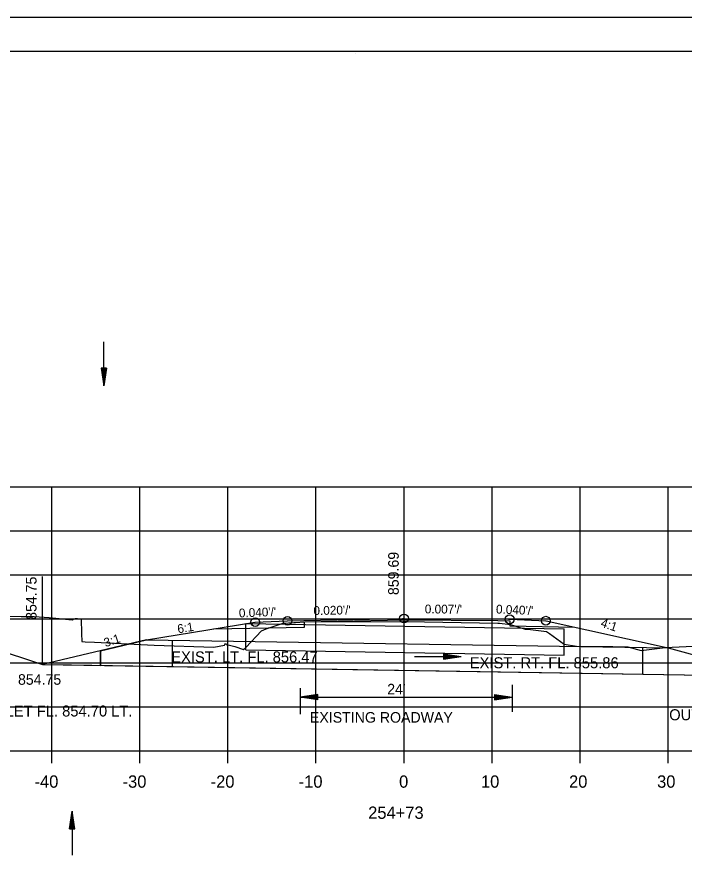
# Model space of a CAD drawing. Extents: x 1486524 to 1499135, y 326561 to 337924.
# Drawn here: x 1488938.9 to 1489014.8, y 328415.9 to 328512.5 of the extents above; entities that cross this region are included whole.
import ezdxf

# ---------------------------------------------------------------- set-up
doc = ezdxf.new("R2010")
doc.units = 0
for name, color, linetype in [('E_Const Align', 7, 'Continuous'), ('E_Const Align Station', 7, 'Continuous'), ('E_Ownership Information', 7, 'Continuous'), ('E_Property Line', 7, 'Continuous'), ('E_Proposed ROW and Easements', 7, 'Continuous'), ('E_Proposed ROW Fig Annot', 7, 'Continuous'), ('E_Quarter Calls', 7, 'Continuous'), ('E_Station Offset', 7, 'Continuous'), ('R_Water Annot', 7, 'Continuous'), ('R_Xsect Elev', 7, 'Continuous'), ('T_Notes', 7, 'Continuous')]:
    doc.layers.add(name, color=color, linetype=linetype)

msp = doc.modelspace()

# ---------------------------------------------------------------- linework, layer by layer
at = {"layer": 'E_Const Align'}
for p, q in [((1488962.883, 328437.793), (1488962.883, 328439.193)), ((1488972.883, 328437.793), (1488972.883, 328439.193)), ((1488982.883, 328437.793), (1488982.883, 328439.193)), ((1488992.883, 328437.793), (1488992.883, 328439.193)), ((1489002.883, 328437.793), (1489002.883, 328439.193)), ((1489012.883, 328437.793), (1489012.883, 328439.193)), ((1488842.885, 328429.191), (1489122.885, 328429.191)), ((1488942.885, 328427.791), (1488942.885, 328429.191)), ((1488952.885, 328427.791), (1488952.885, 328429.191)), ((1488962.885, 328427.791), (1488962.885, 328429.191)), ((1488972.885, 328427.791), (1488972.885, 328429.191)), ((1488982.885, 328427.791), (1488982.885, 328429.191)), ((1488992.885, 328427.791), (1488992.885, 328429.191)), ((1489002.885, 328427.791), (1489002.885, 328429.191)), ((1489012.885, 328427.791), (1489012.885, 328429.191))]:
    msp.add_line(p, q, dxfattribs=at)
at = {"layer": 'E_Ownership Information'}
for p, q in [((1488842.885, 328459.191), (1489122.885, 328459.191)), ((1488942.885, 328429.191), (1488942.885, 328459.191)), ((1488952.885, 328429.191), (1488952.885, 328459.191)), ((1488962.885, 328429.191), (1488962.885, 328459.191)), ((1488972.885, 328429.191), (1488972.885, 328459.191)), ((1488982.885, 328429.191), (1488982.885, 328459.191)), ((1488992.885, 328429.191), (1488992.885, 328459.191)), ((1489002.885, 328429.191), (1489002.885, 328459.191)), ((1489012.885, 328429.191), (1489012.885, 328459.191)), ((1488842.885, 328454.191), (1489122.885, 328454.191)), ((1488842.885, 328449.191), (1489122.885, 328449.191)), ((1488842.885, 328444.191), (1489122.885, 328444.191)), ((1488842.885, 328439.191), (1489122.885, 328439.191)), ((1488842.885, 328434.191), (1489122.885, 328434.191)), ((1488842.885, 328429.191), (1489122.885, 328429.191))]:
    msp.add_line(p, q, dxfattribs=at)
at = {"layer": 'E_Property Line'}
for p, q in [((1488824.885, 328508.651), (1489141.065, 328508.651)), ((1488977.405, 328508.391), (1488977.405, 328508.391)), ((1488977.405, 328508.391), (1488977.405, 328508.391))]:
    msp.add_line(p, q, dxfattribs=at)
at = {"layer": 'E_Proposed ROW and Easements'}
for p, q in [((1488964.913, 328440.663), (1488964.913, 328443.663)), ((1488964.913, 328443.663), (1489001.073, 328443.053)), ((1489001.073, 328440.053), (1489001.073, 328443.053)), ((1488964.913, 328440.663), (1489001.073, 328440.053)), ((1488995.154, 328436.671), (1488995.154, 328433.603)), ((1488971.086, 328436.285), (1488971.086, 328433.333)), ((1488973.086, 328435.584), (1488971.086, 328435.284)), ((1488973.086, 328435.534), (1488971.42, 328435.284)), ((1488973.086, 328435.483), (1488971.764, 328435.284)), ((1488973.086, 328435.433), (1488972.097, 328435.284)), ((1488973.086, 328435.382), (1488972.436, 328435.284)), ((1488973.086, 328434.984), (1488973.086, 328435.584)), ((1488993.154, 328435.589), (1488995.154, 328435.289)), ((1488993.154, 328435.589), (1488993.154, 328434.989)), ((1488993.154, 328435.539), (1488994.82, 328435.289)), ((1488993.154, 328435.488), (1488994.476, 328435.289)), ((1488993.154, 328435.438), (1488994.143, 328435.289)), ((1488993.154, 328435.386), (1488993.804, 328435.289)), ((1488973.086, 328434.984), (1488971.086, 328435.284)), ((1488973.086, 328435.034), (1488971.42, 328435.284)), ((1488973.086, 328435.085), (1488971.764, 328435.284)), ((1488973.086, 328435.135), (1488972.097, 328435.284)), ((1488973.086, 328435.187), (1488972.436, 328435.284)), ((1488973.086, 328435.331), (1488972.77, 328435.284)), ((1488973.086, 328435.237), (1488972.77, 328435.284)), ((1488993.154, 328435.336), (1488993.47, 328435.289)), ((1488993.154, 328434.989), (1488995.154, 328435.289)), ((1488993.154, 328435.191), (1488993.804, 328435.289)), ((1488993.154, 328435.09), (1488994.476, 328435.289)), ((1488993.154, 328435.039), (1488994.82, 328435.289)), ((1488993.154, 328435.14), (1488994.143, 328435.289)), ((1488993.154, 328435.242), (1488993.47, 328435.289))]:
    msp.add_line(p, q, dxfattribs=at)
at = {"layer": 'E_Proposed ROW Fig Annot'}
for p, q in [((1488948.5, 328472.648), (1488948.8, 328470.648)), ((1488949.1, 328472.648), (1488948.5, 328472.648)), ((1488948.5, 328472.648), (1488948.8, 328470.648)), ((1488949.1, 328472.648), (1488948.5, 328472.648)), ((1488948.55, 328472.648), (1488948.8, 328470.982)), ((1488948.55, 328472.648), (1488948.8, 328470.982)), ((1488948.601, 328472.648), (1488948.8, 328471.326)), ((1488948.601, 328472.648), (1488948.8, 328471.326)), ((1488948.651, 328472.648), (1488948.8, 328471.659)), ((1488948.651, 328472.648), (1488948.8, 328471.659)), ((1488948.702, 328472.648), (1488948.8, 328471.998)), ((1488948.702, 328472.648), (1488948.8, 328471.998)), ((1488948.753, 328472.648), (1488948.8, 328472.332)), ((1488948.753, 328472.648), (1488948.8, 328472.332)), ((1488949.1, 328472.648), (1488948.8, 328470.648)), ((1488948.897, 328472.648), (1488948.8, 328471.998)), ((1488948.999, 328472.648), (1488948.8, 328471.326)), ((1488949.05, 328472.648), (1488948.8, 328470.982)), ((1488948.949, 328472.648), (1488948.8, 328471.659)), ((1488948.847, 328472.648), (1488948.8, 328472.332)), ((1488949.1, 328472.648), (1488948.8, 328470.648)), ((1488948.897, 328472.648), (1488948.8, 328471.998)), ((1488948.999, 328472.648), (1488948.8, 328471.326)), ((1488949.05, 328472.648), (1488948.8, 328470.982)), ((1488948.949, 328472.648), (1488948.8, 328471.659)), ((1488948.847, 328472.648), (1488948.8, 328472.332)), ((1488953.653, 328441.804), (1489012.884, 328440.868)), ((1488956.553, 328441.738), (1488956.553, 328438.738)), ((1488948.403, 328440.558), (1488948.403, 328438.888)), ((1488987.378, 328440.195), (1488989.378, 328439.895)), ((1488987.378, 328440.195), (1488987.378, 328439.595)), ((1489009.983, 328440.913), (1489009.983, 328437.897)), ((1488987.378, 328440.145), (1488989.044, 328439.895)), ((1488987.378, 328440.094), (1488988.7, 328439.895)), ((1488987.378, 328440.044), (1488988.367, 328439.895)), ((1488987.378, 328439.992), (1488988.028, 328439.895)), ((1488987.378, 328439.942), (1488987.694, 328439.895)), ((1488987.378, 328439.595), (1488989.378, 328439.895)), ((1488987.378, 328439.797), (1488988.028, 328439.895)), ((1488987.378, 328439.696), (1488988.7, 328439.895)), ((1488987.378, 328439.645), (1488989.044, 328439.895)), ((1488987.378, 328439.746), (1488988.367, 328439.895)), ((1488987.378, 328439.848), (1488987.694, 328439.895)), ((1488941.814, 328438.994), (1489022.333, 328437.698)), ((1488971.086, 328435.284), (1488995.154, 328435.289)), ((1488944.885, 328420.312), (1488945.185, 328422.312)), ((1488944.935, 328420.312), (1488945.185, 328421.978)), ((1488945.485, 328420.312), (1488945.185, 328422.312)), ((1488945.435, 328420.312), (1488945.185, 328421.978)), ((1488944.986, 328420.312), (1488945.185, 328421.634)), ((1488945.036, 328420.312), (1488945.185, 328421.301)), ((1488945.088, 328420.312), (1488945.185, 328420.962)), ((1488945.384, 328420.312), (1488945.185, 328421.634)), ((1488945.334, 328420.312), (1488945.185, 328421.301)), ((1488945.283, 328420.312), (1488945.185, 328420.962)), ((1488944.885, 328420.312), (1488945.485, 328420.312)), ((1488945.138, 328420.312), (1488945.185, 328420.628)), ((1488945.232, 328420.312), (1488945.185, 328420.628))]:
    msp.add_line(p, q, dxfattribs=at)
at = {"layer": 'E_Quarter Calls'}
msp.add_line((1488812.485, 328512.546), (1489145.818, 328512.546), dxfattribs=at)
for points in [[(1488812.478, 328512.546), (1489145.818, 328512.546), (1489145.818, 328299.208), (1488812.478, 328299.208)], [(1489058.805, 328508.651), (1489058.805, 328498.771), (1489094.538, 328498.771), (1489094.538, 328495.851), (1489117.737, 328495.851), (1489117.737, 328471.518), (1489141.065, 328471.518), (1489141.065, 328303.191), (1488824.885, 328303.191), (1488824.885, 328508.651)]]:
    msp.add_lwpolyline(points, close=True, dxfattribs=at)
for centre in [(1488969.653, 328443.949), (1488994.885, 328444.126), (1488994.885, 328444.126)]:
    msp.add_circle(centre, 0.5, dxfattribs=at)
at = {"layer": 'E_Station Offset'}
msp.add_line((1488953.653, 328441.804), (1488941.814, 328438.994), dxfattribs=at)
at = {"layer": 'R_Water Annot'}
for p, q in [((1488948.8, 328470.648), (1488948.8, 328475.648)), ((1488984.079, 328439.899), (1488989.079, 328439.899)), ((1488945.185, 328422.312), (1488945.185, 328417.312))]:
    msp.add_line(p, q, dxfattribs=at)
at = {"layer": 'R_Xsect Elev'}
for p, q in [((1488982.885, 328443.876), (1488982.885, 328453.876)), ((1488941.814, 328438.994), (1488941.814, 328448.974))]:
    msp.add_line(p, q, dxfattribs=at)
at = {"layer": 'T_Notes'}
for p, q in [((1488948.8, 328470.648), (1488948.8, 328475.648)), ((1488948.5, 328472.648), (1488948.8, 328470.648)), ((1488949.1, 328472.648), (1488948.5, 328472.648)), ((1488948.5, 328472.648), (1488948.8, 328470.648)), ((1488949.1, 328472.648), (1488948.5, 328472.648)), ((1488948.55, 328472.648), (1488948.8, 328470.982)), ((1488948.55, 328472.648), (1488948.8, 328470.982)), ((1488948.601, 328472.648), (1488948.8, 328471.326)), ((1488948.601, 328472.648), (1488948.8, 328471.326)), ((1488948.651, 328472.648), (1488948.8, 328471.659)), ((1488948.651, 328472.648), (1488948.8, 328471.659)), ((1488948.702, 328472.648), (1488948.8, 328471.998)), ((1488948.702, 328472.648), (1488948.8, 328471.998)), ((1488948.753, 328472.648), (1488948.8, 328472.332)), ((1488948.753, 328472.648), (1488948.8, 328472.332)), ((1488949.1, 328472.648), (1488948.8, 328470.648)), ((1488948.897, 328472.648), (1488948.8, 328471.998)), ((1488948.999, 328472.648), (1488948.8, 328471.326)), ((1488949.05, 328472.648), (1488948.8, 328470.982)), ((1488948.949, 328472.648), (1488948.8, 328471.659)), ((1488948.847, 328472.648), (1488948.8, 328472.332)), ((1488949.1, 328472.648), (1488948.8, 328470.648)), ((1488948.897, 328472.648), (1488948.8, 328471.998)), ((1488948.999, 328472.648), (1488948.8, 328471.326)), ((1488949.05, 328472.648), (1488948.8, 328470.982)), ((1488948.949, 328472.648), (1488948.8, 328471.659)), ((1488948.847, 328472.648), (1488948.8, 328472.332)), ((1488964.913, 328440.663), (1488964.913, 328443.663)), ((1488964.913, 328443.663), (1489001.073, 328443.053)), ((1488971.586, 328443.241), (1488971.586, 328443.241)), ((1489001.073, 328440.053), (1489001.073, 328443.053)), ((1488953.653, 328441.804), (1489012.884, 328440.868)), ((1488956.553, 328441.738), (1488956.553, 328438.738)), ((1488964.913, 328440.663), (1489001.073, 328440.053)), ((1488987.378, 328440.195), (1488989.378, 328439.895)), ((1488987.378, 328440.195), (1488987.378, 328439.595)), ((1489009.983, 328440.913), (1489009.983, 328437.897)), ((1488984.079, 328439.899), (1488989.079, 328439.899)), ((1488987.378, 328440.145), (1488989.044, 328439.895)), ((1488987.378, 328440.094), (1488988.7, 328439.895)), ((1488987.378, 328440.044), (1488988.367, 328439.895)), ((1488987.378, 328439.992), (1488988.028, 328439.895)), ((1488987.378, 328439.942), (1488987.694, 328439.895)), ((1488987.378, 328439.595), (1488989.378, 328439.895)), ((1488987.378, 328439.797), (1488988.028, 328439.895)), ((1488987.378, 328439.696), (1488988.7, 328439.895)), ((1488987.378, 328439.645), (1488989.044, 328439.895)), ((1488987.378, 328439.746), (1488988.367, 328439.895)), ((1488987.378, 328439.848), (1488987.694, 328439.895)), ((1488945.123, 328438.941), (1489022.333, 328437.698)), ((1488962.883, 328437.793), (1488962.883, 328439.193)), ((1488972.883, 328437.793), (1488972.883, 328439.193)), ((1488982.883, 328437.793), (1488982.883, 328439.193)), ((1488992.883, 328437.793), (1488992.883, 328439.193)), ((1489002.883, 328437.793), (1489002.883, 328439.193)), ((1489012.883, 328437.793), (1489012.883, 328439.193)), ((1488995.154, 328436.671), (1488995.154, 328433.603)), ((1488971.086, 328436.285), (1488971.086, 328433.333)), ((1488973.086, 328435.584), (1488971.086, 328435.284)), ((1488973.086, 328435.534), (1488971.42, 328435.284)), ((1488973.086, 328435.483), (1488971.764, 328435.284)), ((1488973.086, 328435.433), (1488972.097, 328435.284)), ((1488973.086, 328435.382), (1488972.436, 328435.284)), ((1488973.086, 328434.984), (1488973.086, 328435.584)), ((1488993.154, 328435.589), (1488995.154, 328435.289)), ((1488993.154, 328435.589), (1488993.154, 328434.989)), ((1488993.154, 328435.539), (1488994.82, 328435.289)), ((1488993.154, 328435.488), (1488994.476, 328435.289)), ((1488993.154, 328435.438), (1488994.143, 328435.289)), ((1488993.154, 328435.386), (1488993.804, 328435.289)), ((1488971.086, 328435.284), (1488995.154, 328435.289)), ((1488973.086, 328434.984), (1488971.086, 328435.284)), ((1488973.086, 328435.034), (1488971.42, 328435.284)), ((1488973.086, 328435.085), (1488971.764, 328435.284)), ((1488973.086, 328435.135), (1488972.097, 328435.284)), ((1488973.086, 328435.187), (1488972.436, 328435.284)), ((1488973.086, 328435.331), (1488972.77, 328435.284)), ((1488973.086, 328435.237), (1488972.77, 328435.284)), ((1488993.154, 328435.336), (1488993.47, 328435.289)), ((1488993.154, 328434.989), (1488995.154, 328435.289)), ((1488993.154, 328435.191), (1488993.804, 328435.289)), ((1488993.154, 328435.09), (1488994.476, 328435.289)), ((1488993.154, 328435.039), (1488994.82, 328435.289)), ((1488993.154, 328435.14), (1488994.143, 328435.289)), ((1488993.154, 328435.242), (1488993.47, 328435.289)), ((1488842.885, 328429.191), (1489122.885, 328429.191)), ((1488942.885, 328427.791), (1488942.885, 328429.191)), ((1488952.885, 328427.791), (1488952.885, 328429.191)), ((1488962.885, 328427.791), (1488962.885, 328429.191)), ((1488972.885, 328427.791), (1488972.885, 328429.191)), ((1488982.885, 328427.791), (1488982.885, 328429.191)), ((1488992.885, 328427.791), (1488992.885, 328429.191)), ((1489002.885, 328427.791), (1489002.885, 328429.191)), ((1489012.885, 328427.791), (1489012.885, 328429.191)), ((1488944.885, 328420.312), (1488945.185, 328422.312)), ((1488944.935, 328420.312), (1488945.185, 328421.978)), ((1488945.485, 328420.312), (1488945.185, 328422.312)), ((1488945.435, 328420.312), (1488945.185, 328421.978)), ((1488944.986, 328420.312), (1488945.185, 328421.634)), ((1488945.036, 328420.312), (1488945.185, 328421.301)), ((1488945.088, 328420.312), (1488945.185, 328420.962)), ((1488945.384, 328420.312), (1488945.185, 328421.634)), ((1488945.334, 328420.312), (1488945.185, 328421.301)), ((1488945.283, 328420.312), (1488945.185, 328420.962)), ((1488944.885, 328420.312), (1488945.485, 328420.312)), ((1488945.138, 328420.312), (1488945.185, 328420.628)), ((1488945.232, 328420.312), (1488945.185, 328420.628))]:
    msp.add_line(p, q, dxfattribs=at)
for points in [[(1488924.201, 328444.819), (1488941.814, 328438.994), (1488945.123, 328438.941), (1488948.403, 328438.888), (1488948.403, 328440.558), (1488953.653, 328441.804), (1488965.953, 328443.793), (1488965.991, 328443.803), (1488969.607, 328443.947), (1488969.653, 328443.949), (1488982.72, 328444.21), (1488982.885, 328444.214), (1488994.732, 328444.128), (1488994.885, 328444.126), (1488994.936, 328444.124), (1488998.989, 328443.962), (1488999.026, 328443.953), (1489012.883, 328440.868), (1489018.133, 328439.435), (1489018.133, 328437.765), (1489023.119, 328437.698), (1489062.966, 328440.404)], [(1488934.619, 328444.556), (1488939.407, 328444.453), (1488940.9, 328444.459), (1488942.589, 328444.333), (1488945.194, 328444.081), (1488945.397, 328444.167), (1488945.53, 328444.208), (1488945.82, 328444.197), (1488946.216, 328444.181), (1488946.251, 328442.503), (1488946.282, 328441.619), (1488946.67, 328441.563), (1488947.73, 328441.513), (1488954.501, 328441.198), (1488961.271, 328440.94), (1488962.497, 328441.181), (1488962.629, 328441.412), (1488962.698, 328441.272), (1488962.899, 328441.21), (1488963.683, 328441.03), (1488964.64, 328440.678), (1488964.921, 328440.927), (1488966.685, 328442.812), (1488967.211, 328443.024), (1488969.173, 328443.681), (1488970.389, 328443.758), (1488970.476, 328443.764), (1488970.544, 328443.767), (1488971.586, 328443.818), (1488982.735, 328443.875), (1488982.931, 328443.876), (1488983.141, 328443.873), (1488993.537, 328443.699), (1488993.729, 328443.677), (1488994.989, 328443.52), (1488996.661, 328443.003), (1488997.264, 328442.946), (1488999.062, 328442.722), (1488999.389, 328442.524), (1489001.087, 328441.294), (1489002.465, 328441.082), (1489004.257, 328441.044), (1489006.613, 328441.021), (1489008.295, 328440.982), (1489009.826, 328440.582), (1489012.538, 328440.92), (1489018.082, 328441.198)], [(1488961.262, 328443.035), (1488971.586, 328443.241), (1488971.586, 328443.821), (1488982.885, 328444.047), (1488993.537, 328443.969), (1488994.895, 328443.959), (1488994.895, 328443.379), (1489002.265, 328443.232)]]:
    msp.add_lwpolyline(points, dxfattribs=at)
for centre in [(1488965.991, 328443.803), (1488969.653, 328443.949), (1488969.653, 328443.949), (1488982.885, 328444.214), (1488982.885, 328444.214), (1488994.885, 328444.126), (1488994.885, 328444.126), (1488998.989, 328443.962), (1488998.989, 328443.962)]:
    msp.add_circle(centre, 0.5, dxfattribs=at)

# ---------------------------------------------------------------- texts
at = {"layer": 'E_Const Align Station'}
for s, p in [('-40', (1488940.924, 328424.991)), ('-30', (1488950.924, 328424.991)), ('-20', (1488960.924, 328424.991)), ('-10', (1488970.924, 328424.991)), ('0', (1488982.324, 328424.991)), ('10', (1488991.624, 328424.991)), ('20', (1489001.624, 328424.991)), ('30', (1489011.624, 328424.991)), ('254+73', (1488978.814, 328421.456)), ('254+73', (1488978.814, 328421.456))]:
    msp.add_text(s, height=1.4, dxfattribs=at).set_placement(p)
at = {"layer": 'E_Proposed ROW and Easements'}
for s, p in [('EXIST. LT. FL. 856.47', (1488956.451, 328439.222)), ('EXIST. RT. FL. 855.86', (1488990.351, 328438.561))]:
    msp.add_text(s, height=1.25, dxfattribs=at).set_placement(p)
at = {"layer": 'E_Proposed ROW Fig Annot'}
for s, p in [("24'", (1488980.974, 328435.592)), ('EXISTING ROADWAY', (1488972.203, 328432.383))]:
    msp.add_text(s, height=1.2, dxfattribs=at).set_placement(p)
at = {"layer": 'R_Water Annot'}
for s, p in [('INLET FL. 854.70 LT.', (1488935.975, 328433.08)), ('OUTLET FL. 853.57 RT.', (1489012.999, 328432.654))]:
    msp.add_text(s, height=1.25, dxfattribs=at).set_placement(p)
at = {"layer": 'R_Xsect Elev'}
msp.add_text('859.69', height=1.2, rotation=90, dxfattribs=at).set_placement((1488982.285, 328446.876))
at = {"layer": 'T_Notes'}
for s, height, rotation, p in [('854.75', 1.2, 90, (1488941.151, 328444.066)), ("0.040'/'", 1, 2.29061, (1488964.151, 328444.329)), ("0.020'/'", 1, 1.14576, (1488972.608, 328444.608)), ("0.007'/'", 1, 359.58244, (1488985.24, 328444.797)), ("0.040'/'", 1, 357.70939, (1488993.314, 328444.79)), ('4:1', 1, 341.56507, (1489005.139, 328443.311)), ('6:1', 1, 9.07877, (1488957.222, 328442.525)), ('3:1', 1, 18.43495, (1488948.987, 328440.954)), ('854.75', 1.2, 360, (1488939.046, 328436.686))]:
    msp.add_text(s, height=height, rotation=rotation, dxfattribs=at).set_placement(p)
for s, height, p in [('EXIST. LT. FL. 856.47', 1.25, (1488956.451, 328439.222)), ('EXIST. RT. FL. 855.86', 1.25, (1488990.351, 328438.561)), ("24'", 1.2, (1488980.974, 328435.592)), ('EXISTING ROADWAY', 1.2, (1488972.203, 328432.383)), ('-40', 1.4, (1488940.924, 328424.991)), ('-30', 1.4, (1488950.924, 328424.991)), ('-20', 1.4, (1488960.924, 328424.991)), ('-10', 1.4, (1488970.924, 328424.991)), ('0', 1.4, (1488982.324, 328424.991)), ('10', 1.4, (1488991.624, 328424.991)), ('20', 1.4, (1489001.624, 328424.991)), ('30', 1.4, (1489011.624, 328424.991))]:
    msp.add_text(s, height=height, dxfattribs=at).set_placement(p)

doc.saveas('drawing.dxf')
